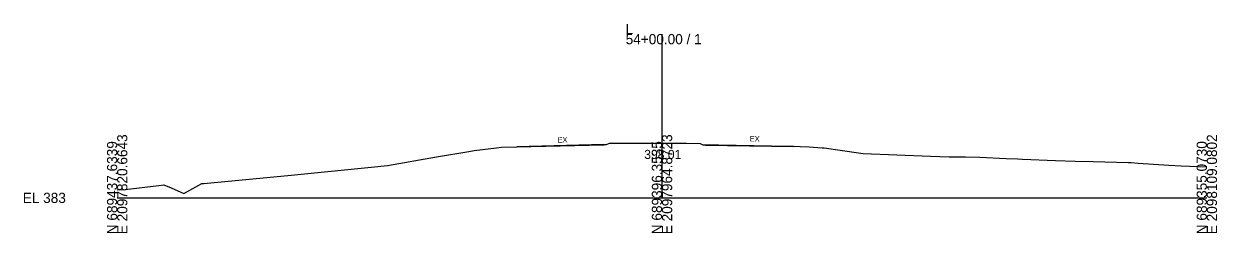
# Model space of a CAD drawing. Extents: x -26 to 8203, y -10 to 9546.
# Drawn here: x 6574.3 to 6902.8, y 490.3 to 547.9 of the extents above; entities that cross this region are included whole.
import ezdxf

# ---------------------------------------------------------------- set-up
doc = ezdxf.new("R2010")
doc.units = 0
for name, color, linetype in [('Default', 7, 'Continuous'), ('Exist CMT Pavement', 7, 'Continuous'), ('Exist Cross Section Cell', 7, 'Continuous'), ('Exist XS Ground Line', 7, 'Continuous'), ('Prop CMT Pvmt Course 1 Wedge', 7, 'Continuous'), ('Prop CMT Pvmt Course 3 Wedge', 7, 'Continuous'), ('Prop XS SE Text', 7, 'Continuous')]:
    doc.layers.add(name, color=color, linetype=linetype)

msp = doc.modelspace()

# ---------------------------------------------------------------- linework, layer by layer
at = {"layer": 'Exist CMT Pavement'}
msp.add_lwpolyline([(6600, 502.26), (6602.16, 502.31), (6611.47, 503.38), (6612.8, 503.57), (6614.82, 502.73), (6618.35, 501.24), (6623.31, 503.94), (6623.82, 503.99), (6647.87, 506.29), (6671.72, 508.68), (6672.61, 508.72), (6674.44, 508.92), (6687.91, 511.27), (6696.83, 512.8), (6698.27, 513.06), (6704.4, 513.77), (6705.83, 513.95), (6710.14, 514.09), (6721.43, 514.39), (6722.09, 514.41), (6722.88, 514.42), (6734.09, 514.65), (6734.76, 514.65), (6735.52, 515.02), (6750, 515.01), (6754.43, 515.01), (6756.78, 515.02), (6760.52, 515), (6761.28, 514.62), (6762.02, 514.62), (6765.54, 514.57), (6775.25, 514.42), (6779.6, 514.34), (6786.24, 514.23), (6788.02, 514.17), (6790.48, 514.09), (6794.07, 513.81), (6794.62, 513.77), (6804.09, 512.41), (6805.35, 512.23), (6823.93, 511.48), (6829.07, 511.33), (6833.57, 511.25), (6837.55, 511.24), (6844.79, 510.86), (6847.95, 510.74), (6849.22, 510.68), (6858.35, 510.33), (6863.79, 510.14), (6868.75, 509.99), (6878.36, 509.73), (6879.16, 509.7), (6881.13, 509.57), (6889.56, 508.96), (6892.94, 508.81), (6900, 508.53)], dxfattribs=at)
at = {"layer": 'Exist Cross Section Cell'}
for p, q in [((6750, 500), (6750, 545.07)), ((6600, 500), (6750, 500)), ((6750, 500), (6900, 500))]:
    msp.add_line(p, q, dxfattribs=at)
at = {"layer": 'Prop CMT Pvmt Course 1 Wedge'}
for p, q in [((6734, 514.53), (6710, 513.96)), ((6734, 514.65), (6734, 514.53)), ((6762, 514.62), (6762, 514.49)), ((6762, 514.49), (6786.19, 514.11))]:
    msp.add_line(p, q, dxfattribs=at)
at = {"layer": 'Prop CMT Pvmt Course 3 Wedge'}
for p, q in [((6734, 514.65), (6710, 514.08)), ((6710, 514.08), (6710, 513.96)), ((6762, 514.62), (6786.19, 514.23)), ((6786.19, 514.23), (6786.19, 514.11))]:
    msp.add_line(p, q, dxfattribs=at)

# ---------------------------------------------------------------- texts
at = {"layer": 'Default'}
msp.add_text('-', height=0.0001, dxfattribs=at).set_placement((6600, 500))
at = {"layer": 'Exist Cross Section Cell'}
for s, p in [('L', (6740, 545.07)), ('54+00.00 / 1', (6740, 542.27)), ('EL 383', (6574, 498.6))]:
    msp.add_text(s, height=2.8, dxfattribs=at).set_placement(p)
for s, p in [('E 2097820.6643', (6602.8, 490)), ('E 2097964.8723', (6752.8, 490)), ('E 2098109.0802', (6902.8, 490)), ('N 689437.6339', (6600, 490)), ('N 689396.3535', (6750, 490)), ('N 689355.0730', (6900, 490))]:
    msp.add_text(s, height=2.8, rotation=90, dxfattribs=at).set_placement(p)
at = {"layer": 'Exist XS Ground Line'}
msp.add_text('398.01', height=2.5, dxfattribs=at).set_placement((6745.1, 510.7))
at = {"layer": 'Prop XS SE Text'}
for rotation, p in [(1.1458, (6721.23, 515.19)), (358.9331, (6774.12, 515.54))]:
    msp.add_text('EX', height=1.5, rotation=rotation, dxfattribs=at).set_placement(p)

doc.saveas('drawing.dxf')
